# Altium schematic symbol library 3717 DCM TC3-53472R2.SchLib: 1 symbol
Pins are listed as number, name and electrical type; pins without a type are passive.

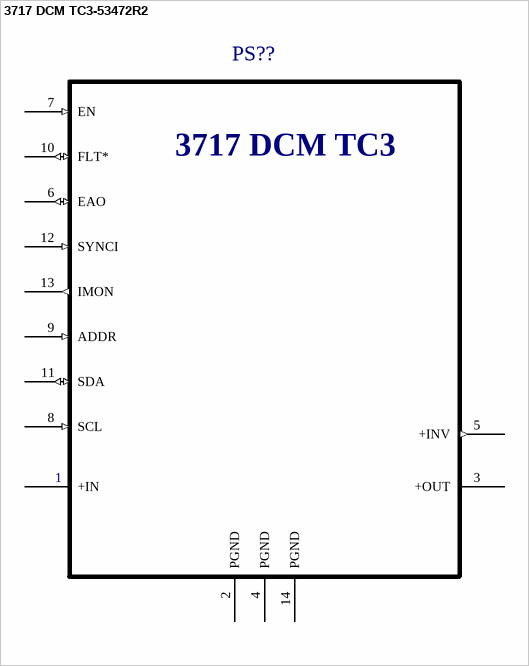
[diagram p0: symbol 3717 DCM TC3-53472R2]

## 3717 DCM TC3-53472R2
designator PS??
PRODUCT OUTLINE 3717 DCM TC3-53472R2; TC NUMBER: TC3
pins: 1 +IN (power), 2 PGND (power), 3 +OUT (power), 4 PGND (power), 5 +INV (out) "PRM OUTPUT", 6 EAO (io), 7 EN (in), 8 SCL (in), 9 ADDR (in), 10 FLT* (io) "FLT/TMON", 11 SDA (io), 12 SYNCI (in), 13 IMON (out), 14 PGND (power)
